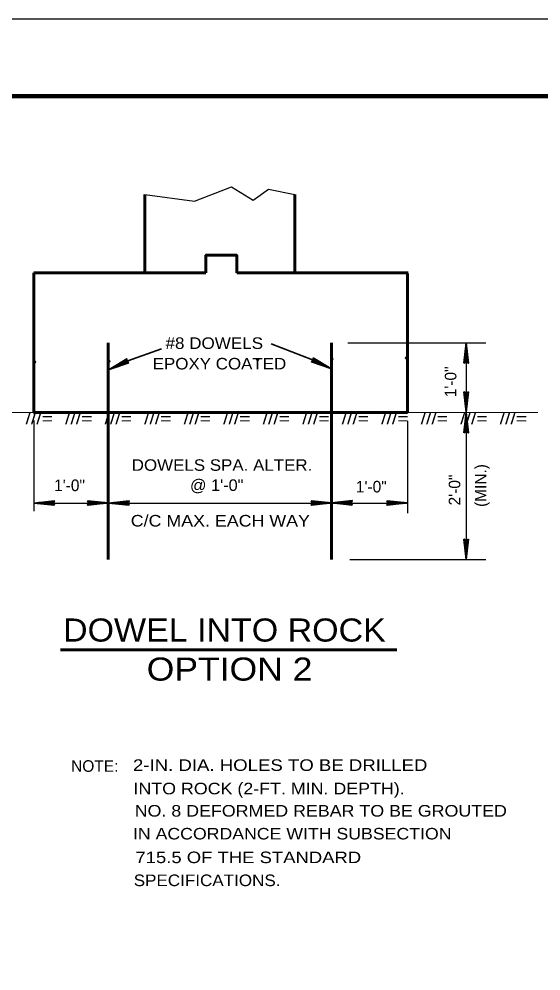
# Model space of a CAD drawing. Extents: x 1.6 to 19.9, y 2.8 to 9.5.
# Drawn here: x 18.709 to 19.239, y 8.58 to 9.545 of the extents above; entities that cross this region are included whole.
import ezdxf
from ezdxf.enums import TextEntityAlignment as Align

# ---------------------------------------------------------------- set-up
doc = ezdxf.new("R2010")
doc.units = 0
doc.header["$LTSCALE"] = 0.0047
doc.header["$PDMODE"] = 32
doc.header["$PDSIZE"] = 0.00235
doc.layers.add('1', color=7, linetype='Continuous', lineweight=35)
doc.layers.add('5', color=7, linetype='Continuous', lineweight=13)

msp = doc.modelspace()

# ---------------------------------------------------------------- linework, layer by layer
at = {"layer": '1', "lineweight": 25}
for p, q in [((19.894917, 9.545083), (16.26675, 9.545083)), ((18.836917, 9.289), (18.836917, 9.2885)), ((18.989167, 9.289), (18.989167, 9.2885)), ((18.724167, 9.05425), (19.10225, 9.05425))]:
    msp.add_line(p, q, dxfattribs=at)
at = {"layer": '1', "lineweight": 60}
for p, q in [((18.724333, 9.28775), (18.898833, 9.28775)), ((18.724333, 9.287667), (18.724333, 9.145917)), ((18.930083, 9.28775), (19.104, 9.28775)), ((19.103417, 9.287167), (19.103417, 9.146)), ((18.799917, 9.21675), (18.799917, 8.996833)), ((19.026167, 9.21675), (19.026167, 8.996833)), ((18.724333, 9.145917), (19.103417, 9.146)), ((18.751417, 8.90525), (19.092417, 8.90525))]:
    msp.add_line(p, q, dxfattribs=at)
at = {"layer": '1'}
for p, q in [((19.160833, 9.196417), (19.162417, 9.211833)), ((19.160833, 9.196333), (19.162583, 9.211833)), ((19.160917, 9.196333), (19.162667, 9.211833)), ((19.161083, 9.196333), (19.162667, 9.21175)), ((19.161167, 9.196333), (19.162917, 9.21175)), ((19.164167, 9.19625), (19.162583, 9.210667)), ((19.16275, 9.196), (19.16275, 9.216667)), ((19.164333, 9.196333), (19.16275, 9.21075)), ((19.164583, 9.196333), (19.163, 9.21075)), ((19.164833, 9.196417), (19.163167, 9.21075)), ((19.007917, 9.201), (19.021333, 9.192833)), ((19.007917, 9.20075), (19.021167, 9.192583)), ((19.008, 9.201083), (19.021417, 9.192917)), ((19.008, 9.201), (19.021417, 9.192917)), ((19.008167, 9.201083), (19.021417, 9.193)), ((18.81975, 9.1985), (18.800917, 9.18975)), ((18.820083, 9.197), (18.805417, 9.191917)), ((18.820167, 9.196667), (18.805417, 9.191583)), ((18.820083, 9.196583), (18.805417, 9.19175)), ((18.820083, 9.1965), (18.805417, 9.191583)), ((18.820167, 9.196417), (18.8055, 9.1915)), ((18.818417, 9.2), (18.806083, 9.192583)), ((18.818583, 9.2), (18.806167, 9.192333)), ((18.818667, 9.19975), (18.806333, 9.19225)), ((18.818833, 9.1995), (18.806417, 9.192)), ((18.8185, 9.19775), (18.810167, 9.19375)), ((19.006417, 9.197667), (19.02025, 9.193)), ((19.006417, 9.1975), (19.020167, 9.192833)), ((19.0065, 9.197917), (19.02025, 9.19325)), ((19.006667, 9.198167), (19.020417, 9.193417)), ((19.006833, 9.1995), (19.02575, 9.190667)), ((19.160833, 9.1665), (19.162417, 9.152)), ((19.161083, 9.1665), (19.162667, 9.152)), ((19.161333, 9.1665), (19.162917, 9.152167)), ((19.1615, 9.1665), (19.163167, 9.15225)), ((19.16275, 9.166917), (19.16275, 9.14625)), ((19.164417, 9.1665), (19.16275, 9.151083)), ((19.164583, 9.1665), (19.162917, 9.151083)), ((19.16475, 9.1665), (19.163083, 9.151)), ((19.164917, 9.1665), (19.163167, 9.151)), ((19.164833, 9.1665), (19.163167, 9.151)), ((19.162917, 9.125333), (19.162917, 9.146)), ((19.160917, 9.12575), (19.162583, 9.14125)), ((19.160917, 9.12575), (19.162667, 9.14125)), ((19.161, 9.12575), (19.162667, 9.14125)), ((19.161167, 9.12575), (19.16275, 9.141083)), ((19.161333, 9.12575), (19.163, 9.141083)), ((19.164167, 9.125667), (19.162667, 9.14)), ((19.164417, 9.12575), (19.162917, 9.140083)), ((19.164667, 9.12575), (19.163083, 9.140167)), ((19.164917, 9.12575), (19.16325, 9.140167)), ((18.744667, 9.05625), (18.73025, 9.054667)), ((18.744667, 9.056), (18.73025, 9.0545)), ((18.74475, 9.05575), (18.730417, 9.05425)), ((18.74475, 9.055583), (18.730417, 9.054)), ((18.779333, 9.05625), (18.794917, 9.0545)), ((18.779333, 9.05625), (18.794917, 9.0545)), ((18.779333, 9.056083), (18.794917, 9.054417)), ((18.779333, 9.055917), (18.794917, 9.054167)), ((18.779417, 9.056333), (18.794917, 9.054667)), ((18.8205, 9.05625), (18.806167, 9.054667)), ((18.8205, 9.056), (18.806167, 9.0545)), ((18.820583, 9.05575), (18.806167, 9.05425)), ((18.820583, 9.055583), (18.806167, 9.054)), ((19.006167, 9.056333), (19.021667, 9.054667)), ((19.006167, 9.05625), (19.021667, 9.0545)), ((19.006167, 9.05625), (19.021667, 9.0545)), ((19.006167, 9.056083), (19.021667, 9.054417)), ((19.006167, 9.055917), (19.021667, 9.054167)), ((19.04675, 9.05625), (19.032417, 9.05475)), ((19.04675, 9.056083), (19.032417, 9.0545)), ((19.046833, 9.055917), (19.032417, 9.054333)), ((19.046833, 9.055667), (19.032417, 9.054083)), ((19.082917, 9.056333), (19.098417, 9.054667)), ((19.082917, 9.05625), (19.098417, 9.0545)), ((19.082917, 9.05625), (19.098417, 9.0545)), ((19.082917, 9.056083), (19.098417, 9.054417)), ((19.082917, 9.055917), (19.098417, 9.054167)), ((18.745167, 9.05425), (18.724417, 9.05425)), ((18.744667, 9.05225), (18.72925, 9.054)), ((18.744667, 9.052333), (18.72925, 9.054)), ((18.744667, 9.05225), (18.72925, 9.053917)), ((18.74475, 9.052667), (18.729333, 9.054333)), ((18.744667, 9.0525), (18.729333, 9.054167)), ((18.778917, 9.054333), (18.799833, 9.054333)), ((18.77925, 9.053), (18.793833, 9.0545)), ((18.779333, 9.05275), (18.793833, 9.054333)), ((18.779333, 9.0525), (18.793917, 9.054083)), ((18.779417, 9.05225), (18.793917, 9.053917)), ((18.821, 9.05425), (18.80025, 9.05425)), ((18.820583, 9.052667), (18.805167, 9.054333)), ((18.8205, 9.0525), (18.805167, 9.054167)), ((18.8205, 9.05225), (18.805167, 9.054)), ((18.8205, 9.052333), (18.805167, 9.054)), ((18.8205, 9.05225), (18.805167, 9.053917)), ((19.00575, 9.054333), (19.026667, 9.054333)), ((19.006083, 9.053), (19.020583, 9.0545)), ((19.006167, 9.05275), (19.020583, 9.054333)), ((19.006167, 9.0525), (19.020667, 9.054083)), ((19.006167, 9.05225), (19.020667, 9.053917)), ((19.04725, 9.054333), (19.0265, 9.054333)), ((19.046833, 9.05275), (19.031417, 9.054417)), ((19.04675, 9.0525), (19.031417, 9.05425)), ((19.04675, 9.052333), (19.031417, 9.054083)), ((19.04675, 9.0525), (19.031417, 9.054083)), ((19.04675, 9.05225), (19.031417, 9.054)), ((19.082417, 9.054333), (19.103333, 9.054333)), ((19.08275, 9.053), (19.097333, 9.0545)), ((19.082917, 9.05275), (19.097333, 9.054333)), ((19.082917, 9.0525), (19.097417, 9.054083)), ((19.082917, 9.05225), (19.097417, 9.053917)), ((19.160917, 9.01725), (19.162583, 9.00275)), ((19.161167, 9.01725), (19.162667, 9.00275)), ((19.161417, 9.01725), (19.162917, 9.002833)), ((19.161667, 9.01725), (19.16325, 9.002917)), ((19.162917, 9.017583), (19.162917, 8.996917)), ((19.164667, 9.01725), (19.162917, 9.001833)), ((19.1645, 9.01725), (19.162917, 9.001833)), ((19.164833, 9.01725), (19.163167, 9.00175)), ((19.164917, 9.01725), (19.16325, 9.00175)), ((19.164917, 9.01725), (19.16325, 9.00175))]:
    msp.add_line(p, q, dxfattribs=at)
at = {"layer": '1', "lineweight": 106}
msp.add_lwpolyline([(19.823, 7.367), (19.823, 9.467), (16.423, 9.467), (16.423, 7.367)], dxfattribs=at)
at = {"layer": '1', "lineweight": 60}
for points in [[(18.914417, 9.305583), (18.898833, 9.305583), (18.898833, 9.287667)], [(18.914417, 9.305583), (18.930083, 9.305583), (18.930083, 9.287667)]]:
    msp.add_lwpolyline(points, dxfattribs=at)
at = {"layer": '1'}
for points in [[(19.1605, 9.196), (19.16275, 9.216667), (19.165167, 9.196), (19.16275, 9.197)], [(18.820667, 9.196333), (18.800917, 9.18975), (18.818667, 9.200583), (18.818667, 9.198)], [(19.00775, 9.2015), (19.02575, 9.190667), (19.005833, 9.197333), (19.007917, 9.199)], [(19.165167, 9.166917), (19.16275, 9.14625), (19.1605, 9.166917), (19.162917, 9.16575)], [(19.163167, 9.1655), (19.163167, 9.15625), (19.162917, 9.156333), (19.163167, 9.158083)], [(19.160583, 9.125333), (19.162917, 9.146), (19.165167, 9.125333), (19.162917, 9.126417)], [(18.745167, 9.052), (18.724417, 9.05425), (18.745167, 9.056583), (18.744, 9.05425)], [(18.778917, 9.056583), (18.799833, 9.054333), (18.778917, 9.052), (18.780083, 9.054333)], [(18.780417, 9.0545), (18.789667, 9.05475), (18.789583, 9.0545), (18.787917, 9.0545), (18.780417, 9.05475), (18.786417, 9.054833), (18.780167, 9.055), (18.784417, 9.055167), (18.779917, 9.055417), (18.787083, 9.054833), (18.796333, 9.0545), (18.794417, 9.053917), (18.797, 9.054167), (18.780417, 9.054083), (18.785167, 9.05375), (18.780167, 9.05375), (18.790667, 9.0545), (18.779917, 9.053417)], [(18.821, 9.052), (18.80025, 9.05425), (18.821, 9.056583), (18.819917, 9.05425)], [(19.00575, 9.056583), (19.026667, 9.054333), (19.00575, 9.052), (19.006833, 9.054333)], [(19.04725, 9.052), (19.0265, 9.054333), (19.04725, 9.056667), (19.046167, 9.054333)], [(19.082417, 9.056583), (19.103333, 9.054333), (19.082417, 9.052), (19.083583, 9.054333)], [(19.083917, 9.0545), (19.093167, 9.05475), (19.093083, 9.0545), (19.091417, 9.0545), (19.083917, 9.05475), (19.089917, 9.054833), (19.083667, 9.055), (19.087917, 9.055167), (19.083417, 9.055417), (19.090583, 9.054833), (19.099833, 9.0545), (19.097917, 9.053917), (19.1005, 9.054167), (19.083917, 9.054083), (19.088667, 9.05375), (19.083667, 9.05375), (19.094167, 9.0545), (19.0835, 9.053417)], [(18.743667, 9.054), (18.7345, 9.053833), (18.7345, 9.054083), (18.736333, 9.054), (18.743667, 9.053833), (18.73775, 9.05375), (18.743917, 9.0535), (18.739583, 9.053417), (18.744167, 9.053167), (18.737083, 9.05375), (18.727917, 9.054083), (18.72975, 9.054667), (18.72725, 9.054417), (18.743667, 9.0545), (18.738917, 9.05475), (18.743917, 9.05475), (18.733417, 9.054), (18.744, 9.055167)], [(19.165167, 9.017583), (19.162917, 8.996917), (19.160583, 9.017583), (19.162917, 9.0165)], [(19.16325, 9.01625), (19.16325, 9.007), (19.163, 9.007), (19.16325, 9.00875)]]:
    msp.add_lwpolyline(points, close=True, dxfattribs=at)
for points in [[(19.162583, 9.197333), (19.162417, 9.206583), (19.162667, 9.2065), (19.162583, 9.20475), (19.162417, 9.197333), (19.16225, 9.20325), (19.162083, 9.197167), (19.162, 9.201417), (19.16175, 9.196917), (19.16225, 9.204), (19.162667, 9.21325), (19.163167, 9.21125), (19.162917, 9.213833), (19.163, 9.197333), (19.163333, 9.20225), (19.163333, 9.197167), (19.162667, 9.207667), (19.163667, 9.197), (19.162667, 9.1975), (19.161167, 9.1965), (19.161417, 9.197), (19.16225, 9.1975), (19.162083, 9.197917), (19.161417, 9.197583), (19.162917, 9.19725), (19.163667, 9.196917), (19.16475, 9.196417)], [(19.00825, 9.199083), (19.016667, 9.195333), (19.0165, 9.195083), (19.015083, 9.196), (19.008333, 9.19925), (19.013833, 9.196833), (19.00825, 9.199667), (19.012167, 9.197917), (19.008167, 9.200083), (19.014417, 9.1965), (19.022667, 9.19225), (19.020667, 9.192583), (19.023167, 9.19175), (19.008, 9.19875), (19.012333, 9.196333), (19.007667, 9.1985), (19.017583, 9.194667), (19.007417, 9.19825), (19.00825, 9.199), (19.008, 9.20075), (19.008333, 9.20025), (19.008417, 9.199333), (19.008917, 9.199333), (19.008917, 9.200083), (19.007917, 9.198833), (19.00725, 9.19825), (19.006417, 9.1975)], [(18.810167, 9.19375), (18.81175, 9.1945), (18.818583, 9.1975), (18.813333, 9.194833), (18.818917, 9.197333), (18.815083, 9.195333), (18.819333, 9.197167), (18.812667, 9.194667), (18.804167, 9.191083), (18.805667, 9.19225), (18.8035, 9.191083), (18.818333, 9.198083), (18.813833, 9.196333), (18.8185, 9.1985), (18.809167, 9.19325), (18.818333, 9.198833), (18.818417, 9.197583), (18.819833, 9.19675), (18.81925, 9.19675), (18.818583, 9.19725), (18.81825, 9.196917), (18.818917, 9.1965), (18.8185, 9.198), (18.8185, 9.198917), (18.818417, 9.2)], [(19.163167, 9.1655), (19.1635, 9.1595), (19.1635, 9.16575), (19.163667, 9.161417), (19.163917, 9.166), (19.163417, 9.158833), (19.162917, 9.149667), (19.162417, 9.151583), (19.162667, 9.149), (19.162667, 9.1655), (19.162333, 9.16075), (19.162333, 9.16575), (19.163083, 9.155167), (19.161833, 9.165917), (19.163083, 9.165417), (19.1645, 9.166333), (19.164167, 9.165917), (19.163417, 9.165417), (19.163583, 9.165), (19.16425, 9.16525), (19.16275, 9.165583), (19.161833, 9.166), (19.160917, 9.1665)], [(19.162667, 9.12675), (19.162417, 9.136), (19.16275, 9.135917), (19.162667, 9.134167), (19.162417, 9.12675), (19.162333, 9.132667), (19.162167, 9.1265), (19.162083, 9.13075), (19.161833, 9.12625), (19.162333, 9.133417), (19.16275, 9.142583), (19.16325, 9.140667), (19.163, 9.14325), (19.163083, 9.12675), (19.163417, 9.131583), (19.163417, 9.1265), (19.162667, 9.137), (19.163833, 9.126333), (19.162667, 9.126833), (19.161167, 9.125917), (19.1615, 9.126333), (19.162333, 9.126833), (19.162167, 9.12725), (19.161417, 9.127), (19.162917, 9.126667), (19.163833, 9.12625), (19.164833, 9.12575)], [(18.743667, 9.054), (18.7445, 9.052583), (18.744, 9.052917), (18.743667, 9.05375), (18.743083, 9.0535), (18.7435, 9.052833), (18.743833, 9.054333), (18.744167, 9.055167), (18.744667, 9.05625)], [(18.780417, 9.0545), (18.7795, 9.056), (18.779917, 9.055667), (18.780417, 9.054833), (18.780917, 9.055083), (18.7805, 9.05575), (18.780167, 9.05425), (18.779833, 9.053417), (18.779417, 9.052333)], [(18.819583, 9.054), (18.810417, 9.053833), (18.810417, 9.054083), (18.812167, 9.054), (18.819583, 9.053833), (18.813667, 9.05375), (18.819833, 9.0535), (18.815417, 9.053417), (18.819917, 9.053167), (18.812917, 9.05375), (18.803667, 9.054083), (18.805583, 9.054667), (18.803083, 9.054417), (18.819583, 9.0545), (18.81475, 9.05475), (18.819833, 9.05475), (18.80925, 9.054), (18.819917, 9.055167), (18.8195, 9.054), (18.820417, 9.052583), (18.819917, 9.052917), (18.8195, 9.05375), (18.818917, 9.0535), (18.819333, 9.052833), (18.819667, 9.054333), (18.820083, 9.055167), (18.8205, 9.05625)], [(19.007167, 9.0545), (19.016417, 9.05475), (19.016417, 9.0545), (19.014667, 9.0545), (19.007167, 9.05475), (19.013167, 9.054833), (19.006917, 9.055), (19.011167, 9.055167), (19.006667, 9.055417), (19.013917, 9.054833), (19.023083, 9.0545), (19.021167, 9.053917), (19.023833, 9.054167), (19.007167, 9.054083), (19.012, 9.05375), (19.006917, 9.05375), (19.017417, 9.0545), (19.00675, 9.053417), (19.00725, 9.0545), (19.006333, 9.056), (19.00675, 9.055667), (19.00725, 9.054833), (19.007667, 9.055083), (19.007333, 9.05575), (19.007, 9.05425), (19.006667, 9.053417), (19.006167, 9.052333)], [(19.045833, 9.054083), (19.036667, 9.053917), (19.036667, 9.054167), (19.038417, 9.054083), (19.045833, 9.053917), (19.039917, 9.05375), (19.046083, 9.053583), (19.041667, 9.0535), (19.046167, 9.05325), (19.039167, 9.05375), (19.029917, 9.054167), (19.031833, 9.05475), (19.029333, 9.0545), (19.045833, 9.0545), (19.041, 9.054833), (19.046083, 9.054833), (19.0355, 9.054083), (19.046167, 9.05525), (19.04575, 9.054083), (19.046667, 9.052667), (19.046167, 9.053), (19.04575, 9.05375), (19.045167, 9.0535), (19.045583, 9.052917), (19.045917, 9.054417), (19.046333, 9.05525), (19.04675, 9.05625)], [(19.083917, 9.0545), (19.083, 9.056), (19.0835, 9.055667), (19.083917, 9.054833), (19.084417, 9.055083), (19.084, 9.05575), (19.083667, 9.05425), (19.083333, 9.053417), (19.082917, 9.052333)], [(19.16325, 9.01625), (19.163583, 9.01025), (19.163583, 9.0165), (19.163667, 9.012167), (19.163917, 9.016667), (19.1635, 9.0095), (19.163, 9.000333), (19.162583, 9.00225), (19.16275, 8.99975), (19.162667, 9.01625), (19.162417, 9.011417), (19.162417, 9.0165), (19.163167, 9.005917), (19.161917, 9.016583), (19.163167, 9.016083), (19.164583, 9.017), (19.16425, 9.016583), (19.1635, 9.016083), (19.163667, 9.015667), (19.164333, 9.016), (19.162917, 9.01625), (19.161917, 9.01675), (19.161, 9.01725)]]:
    msp.add_lwpolyline(points, dxfattribs=at)
msp.add_point((18.810167, 9.19375), dxfattribs=at)
at = {"layer": '5', "lineweight": 60}
for p, q in [((18.836917, 9.289), (18.836917, 9.367167)), ((18.989167, 9.289), (18.989167, 9.367167))]:
    msp.add_line(p, q, dxfattribs=at)
at = {"layer": '5', "lineweight": 35}
for p, q in [((18.81975, 9.1985), (18.853917, 9.210667)), ((19.006833, 9.1995), (18.965167, 9.215583))]:
    msp.add_line(p, q, dxfattribs=at)
at = {"layer": '5', "lineweight": 25}
for p, q in [((19.04275, 9.21675), (19.182917, 9.21675)), ((19.162917, 9.21625), (19.162917, 8.99675)), ((18.724333, 9.145917), (18.724333, 9.1445)), ((19.103417, 9.146), (19.103417, 9.1455)), ((19.103417, 9.146), (19.103833, 9.146)), ((18.724333, 9.137917), (18.724333, 9.046)), ((19.103417, 9.13725), (19.103417, 9.043917)), ((19.044917, 8.996833), (19.182917, 8.996833))]:
    msp.add_line(p, q, dxfattribs=at)
at = {"layer": '5'}
for p, q in [((18.800167, 9.1565), (18.799, 9.081667)), ((18.5095, 9.145917), (19.235667, 9.145917)), ((18.800583, 9.06), (18.80025, 9.13475)), ((19.02725, 9.06325), (19.026333, 9.138083)), ((19.025083, 9.0775), (19.026083, 9.002667))]:
    msp.add_line(p, q, dxfattribs=at)
at = {"layer": '5', "lineweight": 25}
msp.add_lwpolyline([(18.836917, 9.367167), (18.887167, 9.360417), (18.92475, 9.37475), (18.946667, 9.3615), (18.962333, 9.3725), (18.989167, 9.367167)], dxfattribs=at)
at = {"layer": '5'}
for p in [(18.951417, 9.199667), (19.026833, 9.200417), (19.10225, 9.20125), (18.72525, 9.19725), (18.800667, 9.198)]:
    msp.add_point(p, dxfattribs=at)

# ---------------------------------------------------------------- texts
at = {"layer": '1'}
msp.add_text('2\'-0"', height=0.01175, rotation=90, dxfattribs=at).set_placement((19.156917, 9.051833))
at = {"layer": '5'}
for s, height, width, p in [('#8 DOWELS', 0.01175, 1.1, (18.857917, 9.2105)), ('EPOXY COATED', 0.01167, 1.1, (18.844917, 9.18975)), ('DOWELS SPA. ALTER.', 0.01167, 1.1, (18.823667, 9.086917)), ('@ 1\'-0"', 0.01175, 1.05, (18.88275, 9.0665)), ('C/C MAX. EACH WAY', 0.01175, 1.15, (18.822667, 9.030417)), ('DOWEL INTO ROCK', 0.02342, 1.1, (18.754, 8.91375)), ('2-IN. DIA. HOLES TO BE DRILLED', 0.01175, 1.2, (18.824917, 8.782583)), ('INTO ROCK (2-FT. MIN. DEPTH).', 0.01175, 1.15, (18.825417, 8.758833)), ('NO. 8 DEFORMED REBAR TO BE GROUTED', 0.01175, 1.15, (18.826667, 8.73625)), ('IN ACCORDANCE WITH SUBSECTION ', 0.01167, 1.15, (18.824917, 8.713083)), ('715.5 OF THE STANDARD', 0.01167, 1.2, (18.827417, 8.689083)), ('SPECIFICATIONS.', 0.01175, 1.1, (18.825667, 8.66575))]:
    msp.add_text(s, height=height, dxfattribs=dict(at, width=width)).set_placement(p)
for s, height, p in [('1\'-0"', 0.01175, (19.152917, 9.1615)), ('(MIN.)', 0.01167, (19.183333, 9.050333))]:
    msp.add_text(s, height=height, rotation=90, dxfattribs=at).set_placement(p)
for s, height, width, p in [('///=', 0.01175, 1.25, (18.729833, 9.134167)), ('///=', 0.01175, 1.25, (18.769917, 9.134167)), ('///=', 0.01175, 1.25, (18.809958, 9.134167)), ('///=', 0.01175, 1.25, (18.850083, 9.134167)), ('///=', 0.01175, 1.25, (18.890167, 9.134167)), ('///=', 0.01175, 1.25, (18.930208, 9.134167)), ('///=', 0.01175, 1.25, (18.970292, 9.134167)), ('///=', 0.01175, 1.25, (19.010417, 9.134167)), ('///=', 0.01175, 1.25, (19.050458, 9.134167)), ('///=', 0.01175, 1.25, (19.0905, 9.134167)), ('///=', 0.01175, 1.25, (19.130583, 9.134167)), ('///=', 0.01175, 1.25, (19.170708, 9.134167)), ('///=', 0.01175, 1.25, (19.21075, 9.134167)), ('OPTION 2', 0.02342, 1.15, (18.922875, 8.874167))]:
    msp.add_text(s, height=height, dxfattribs=dict(at, width=width)).set_placement(p, align=Align.CENTER)
for p in [(18.744917, 9.066333), (19.051, 9.065)]:
    msp.add_text('1\'-0"', height=0.01175, dxfattribs=at).set_placement(p)
msp.add_text('NOTE:', height=0.01175, dxfattribs=at).set_placement((18.810167, 8.781667), align=Align.RIGHT)

doc.saveas('drawing.dxf')
